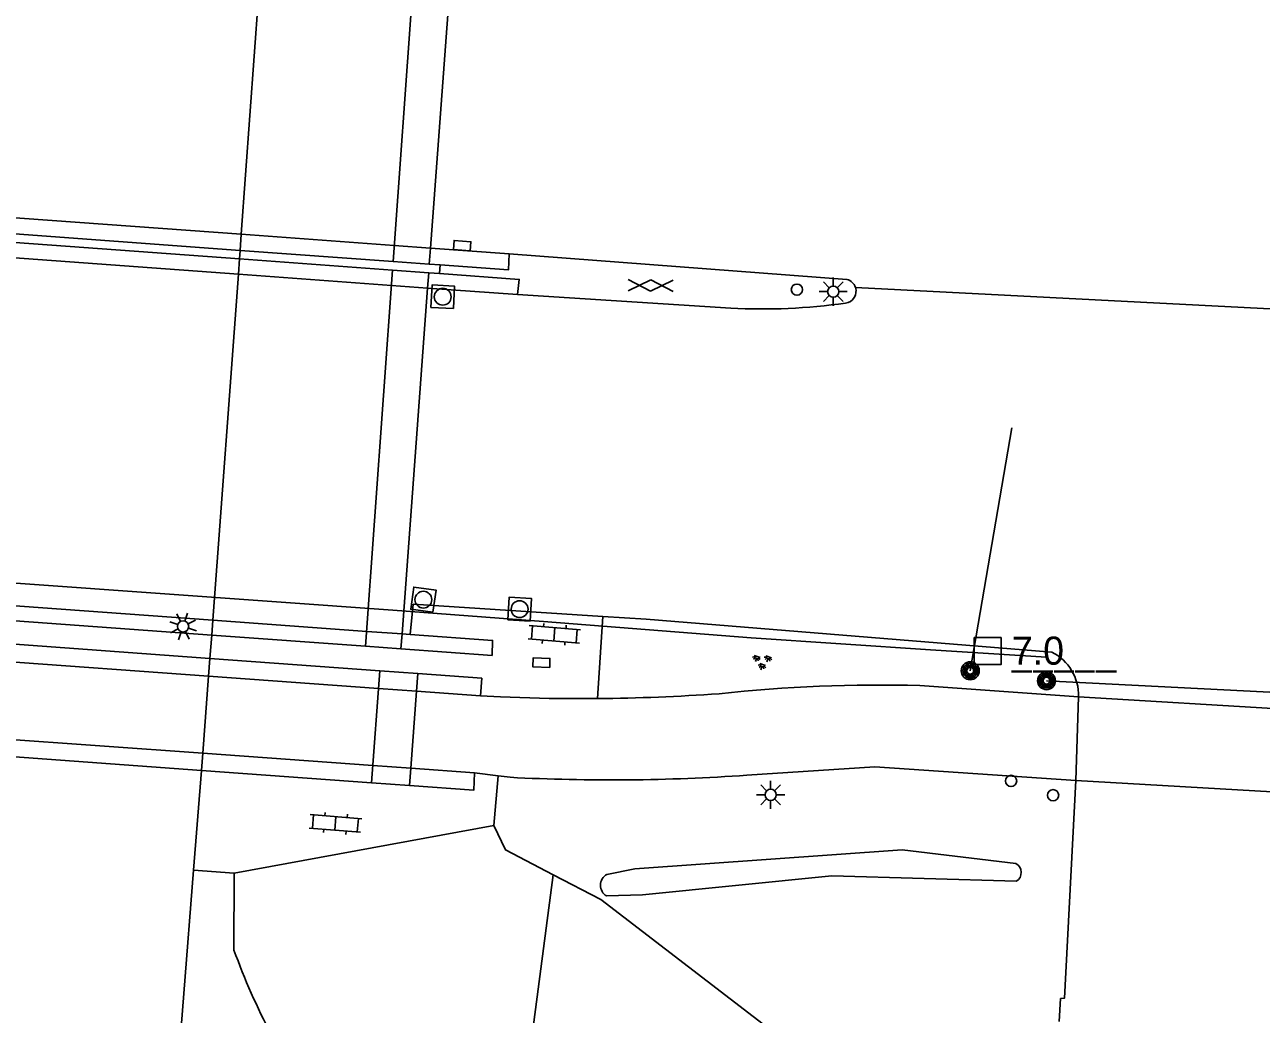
# Model space of a CAD drawing. Extents: x 133000 to 136000, y 400500 to 403500.
# Drawn here: x 133137.7 to 133192.8, y 401011.6 to 401055.6 of the extents above; entities that cross this region are included whole.
import ezdxf

# ---------------------------------------------------------------- set-up
doc = ezdxf.new("R2010")
doc.units = 0
for name, color, linetype in [('gg-knt-BGT kruinlijn', 7, 'Continuous'), ('gg-knt-bovenkant onderkant talud', 7, 'Continuous'), ('gg-knt-verharding', 7, 'Continuous'), ('gg-knt-verharding nz', 7, 'Continuous'), ('gg-kntw-greppel-droge sloot', 7, 'Continuous'), ('gg-kwrk-kunstwerk', 7, 'Continuous'), ('gg-kwrk-kunstwerk niveau 01', 7, 'Continuous'), ('gt-anno-nummer hm paal', 7, 'Continuous'), ('gt-grn-groengrens', 7, 'Continuous'), ('gt-grn-weggrens', 7, 'Continuous'), ('gt-knt-geleideconstructie', 7, 'Continuous'), ('gt-knt-lijn portaal', 7, 'Continuous'), ('gt-symb-drukknoppaal', 7, 'Continuous'), ('gt-symb-gesloten verharding', 7, 'Continuous'), ('gt-symb-groenvak', 7, 'Continuous'), ('gt-symb-hm paal', 7, 'Continuous'), ('gt-symb-klinker verharding', 7, 'Continuous'), ('gt-symb-kolk', 7, 'Continuous'), ('gt-symb-kolk center center', 7, 'Continuous'), ('gt-symb-lichtmast', 7, 'Continuous'), ('gt-symb-portaalmast', 7, 'Continuous'), ('gt-symb-rioolschacht', 7, 'Continuous'), ('gt-symb-verkeersregelinstallatiepaal', 7, 'Continuous')]:
    doc.layers.add(name, color=color, linetype=linetype)

# ---------------------------------------------------------------- blocks, each defined once
blk = doc.blocks.new('gt0-GESVH1')
at = {"layer": 'gt-symb-gesloten verharding'}
for p, q in [((-0.992, -0.261), (0.008, 0.239)), ((0.008, -0.261), (-0.992, 0.239)), ((0.008, 0.239), (1.008, -0.261)), ((1.008, 0.239), (0.008, -0.261))]:
    blk.add_line(p, q, dxfattribs=at)
blk = doc.blocks.new('gt0-GRVAK')
at = {"layer": 'gt-symb-groenvak'}
for p, q in [((-0.11, 0.189), (-0.228, 0.24)), ((-0.182, 0.153), (0.088, 0.153)), ((-0.091, 0.211), (-0.156, 0.322)), ((-0.047, 0.214), (-0.047, 0.393)), ((-0.004, 0.211), (0.061, 0.322)), ((0.015, 0.189), (0.133, 0.24)), ((0.262, -0.052), (0.197, 0.059)), ((0.305, -0.049), (0.305, 0.13)), ((0.349, -0.052), (0.414, 0.059)), ((-0.245, -0.228), (-0.363, -0.177)), ((-0.318, -0.264), (-0.047, -0.264)), ((-0.226, -0.206), (-0.291, -0.095)), ((-0.183, -0.203), (-0.183, -0.024)), ((-0.139, -0.206), (-0.074, -0.095)), ((-0.12, -0.228), (-0.002, -0.177)), ((0.243, -0.074), (0.125, -0.023)), ((0.17, -0.11), (0.441, -0.11)), ((0.368, -0.074), (0.486, -0.023))]:
    blk.add_line(p, q, dxfattribs=at)
blk = doc.blocks.new('gt0-VIPAAL')
at = {"layer": 'gt-symb-verkeersregelinstallatiepaal'}
blk.add_circle((0, 0), 0.25, dxfattribs=at)
blk = doc.blocks.new('gt0-LMAST')
at = {"layer": 'gt-symb-lichtmast'}
for p, q in [((-0.005, 0.246), (-0.005, 0.621)), ((-0.182, 0.173), (-0.447, 0.438)), ((0.172, 0.173), (0.437, 0.438)), ((-0.255, -0.004), (-0.63, -0.004)), ((-0.182, -0.181), (-0.447, -0.446)), ((-0.005, -0.254), (-0.005, -0.629)), ((0.437, -0.446), (0.172, -0.181)), ((0.245, -0.004), (0.62, -0.004))]:
    blk.add_line(p, q, dxfattribs=at)
blk.add_circle((-0.005, -0.004), 0.25, dxfattribs=at)
blk = doc.blocks.new('gt0-PORTM')
at = {"layer": 'gt-symb-portaalmast'}
for radius in [0.4, 0.33, 0.27, 0.21, 0.15]:
    blk.add_circle((0, 0), radius, dxfattribs=at)
blk = doc.blocks.new('gt0-HMpaal')
at = {"layer": 'gt-symb-hm paal'}
blk.add_lwpolyline([(-0.6, 0.6), (0.6, 0.6), (0.6, -0.6), (-0.6, -0.6)], close=True, dxfattribs=at)
blk = doc.blocks.new('gt0-DPAAL')
at = {"layer": 'gt-symb-drukknoppaal'}
blk.add_circle((0, 0), 0.25, dxfattribs=at)
blk = doc.blocks.new('gt0-KOLK')
at = {"layer": 'gt-symb-kolk'}
blk.add_lwpolyline([(0, 0), (0.375, 0), (0.375, 0.4), (-0.375, 0.4), (-0.375, 0), (0, 0)], dxfattribs=at)
blk = doc.blocks.new('gt0-KOLKCC')
at = {"layer": 'gt-symb-kolk center center'}
blk.add_lwpolyline([(-0.375, 0.2), (0.375, 0.2), (0.375, -0.2), (-0.375, -0.2)], close=True, dxfattribs=at)
blk = doc.blocks.new('gt0-KL1')
at = {"layer": 'gt-symb-klinker verharding'}
for p, q in [((-1.15, 0.3), (1.15, 0.3)), ((-1, -0.3), (-1, 0.3)), ((-0.5, 0.3), (-0.5, 0.45)), ((0, -0.3), (0, 0.3)), ((0.5, 0.3), (0.5, 0.45)), ((1, -0.3), (1, 0.3)), ((-1.15, -0.3), (1.15, -0.3)), ((-0.5, -0.45), (-0.5, -0.3)), ((0.5, -0.45), (0.5, -0.3))]:
    blk.add_line(p, q, dxfattribs=at)
blk = doc.blocks.new('gt0-RS')
at = {"layer": 'gt-symb-rioolschacht'}
blk.add_lwpolyline([(-0.5, -0.5), (0.5, -0.5), (0.5, 0.5), (-0.5, 0.5)], close=True, dxfattribs=at)
blk.add_circle((0, 0), 0.375, dxfattribs=at)

msp = doc.modelspace()

# ---------------------------------------------------------------- linework, layer by layer
at = {"layer": 'gg-knt-BGT kruinlijn'}
msp.add_lwpolyline([(133179.897, 401002.606), (133179.501, 401003.732), (133174.882, 401007.87), (133163.368, 401016.705), (133161.251, 401017.809)], dxfattribs=at)
at = {"layer": 'gg-knt-bovenkant onderkant talud'}
msp.add_line((133147.055, 401017.874), (133147.04, 401014.454), dxfattribs=at)
msp.add_lwpolyline([(133161.251, 401017.809), (133159.133, 401018.912), (133158.61, 401020.001)], dxfattribs=at)
msp.add_arc((133175.322, 401024.718), 30.087, 199.9466, 215.6251, dxfattribs=at)
at = {"layer": 'gg-knt-verharding'}
for p, q in [((133147.314, 401045.592), (133147.285, 401045.211)), ((133159.294, 401045.442), (133174.33, 401044.296)), ((133156.182, 401044.561), (133156.213, 401044.942)), ((133169.152, 401043.022), (133159.656, 401043.622)), ((133163.457, 401029.305), (133163.228, 401025.65)), ((133146.047, 401028.475), (133145.97, 401027.433)), ((133184.638, 401025.73), (133177.577, 401026.226)), ((133145.593, 401022.453), (133145.244, 401018.006)), ((133158.803, 401022.211), (133157.754, 401022.344)), ((133158.61, 401020.001), (133158.803, 401022.211)), ((133159.328, 401022.144), (133158.803, 401022.211)), ((133158.61, 401020.001), (133147.055, 401017.874)), ((133147.055, 401017.874), (133145.244, 401018.006)), ((133183.774, 401011.281), (133183.829, 401012.309))]:
    msp.add_line(p, q, dxfattribs=at)
for points in [[(133154.89, 401028.498), (133155.019, 401029.848), (133163.457, 401029.305)], [(133163.457, 401029.305), (133165.388, 401029.181), (133183.442, 401027.719)], [(133163.228, 401025.65), (133161.065, 401025.658), (133158.908, 401025.719), (133158.02, 401025.766)], [(133184.521, 401021.999), (133175.568, 401022.61), (133169.875, 401022.239)], [(133183.829, 401012.309), (133184.006, 401012.313), (133184.521, 401021.999)], [(133145.244, 401018.006), (133143.952, 401001.542), (133140.687, 400961.849), (133137.071, 400921.674), (133133.793, 400886.411), (133130.554, 400853.339), (133126.957, 400817.784)]]:
    msp.add_lwpolyline(points, dxfattribs=at)
for centre, radius, start, end in [((133174.2, 401043.777), 0.535, 18.1891, 75.8905), ((133174.198, 401043.776), 0.537, 277.3466, 18.2315), ((133170.576, 401069.26), 26.277, 266.8945, 278.0758), ((133182.472, 401025.781), 2.167, 358.64, 63.3976), ((133162.512, 401112.929), 87.282, 270.46972, 274.02176), ((133175.835, 400958.995), 67.254, 88.51538, 96.14618), ((133163.822, 401108.741), 86.714, 267.02932, 274.00281)]:
    msp.add_arc(centre, radius, start, end, dxfattribs=at)
at = {"layer": 'gg-knt-verharding nz'}
for p, q in [((133148.349, 401059.962), (133147.366, 401046.307)), ((133147.366, 401046.307), (133147.314, 401045.592)), ((133147.285, 401045.211), (133147.235, 401044.53)), ((133147.235, 401044.53), (133146.096, 401029.137)), ((133146.096, 401029.137), (133146.047, 401028.475)), ((133145.97, 401027.433), (133145.912, 401026.643)), ((133145.912, 401026.643), (133145.652, 401023.215)), ((133184.521, 401021.999), (133184.638, 401025.73)), ((133184.638, 401025.73), (133202.437, 401024.645)), ((133145.652, 401023.215), (133145.593, 401022.453)), ((133184.521, 401021.999), (133197.902, 401021.238))]:
    msp.add_line(p, q, dxfattribs=at)
at = {"layer": 'gg-kntw-greppel-droge sloot'}
for points in [[(133181.852, 401018.306), (133176.785, 401018.914), (133164.887, 401018.07), (133163.635, 401017.825)], [(133163.626, 401016.864), (133165.222, 401016.917), (133173.648, 401017.762), (133181.87, 401017.52)]]:
    msp.add_lwpolyline(points, dxfattribs=at)
for centre, radius, start, end in [((133181.636, 401017.908), 0.453, 301.0724, 61.5514), ((133163.914, 401017.342), 0.558, 119.9866, 238.9402)]:
    msp.add_arc(centre, radius, start, end, dxfattribs=at)
at = {"layer": 'gg-kwrk-kunstwerk'}
for p, q in [((133155.199, 401060.151), (133154.123, 401045.095)), ((133155.789, 401045.696), (133159.294, 401045.442)), ((133154.095, 401044.713), (133152.9, 401027.977)), ((133155.708, 401044.596), (133156.182, 401044.561)), ((133156.213, 401044.942), (133155.736, 401044.977)), ((133155.658, 401043.914), (133159.656, 401043.622)), ((133154.523, 401028.525), (133154.89, 401028.498)), ((133153.533, 401026.882), (133153.169, 401021.901)), ((133158.02, 401025.766), (133155.164, 401025.973)), ((133157.754, 401022.344), (133154.906, 401022.549))]:
    msp.add_line(p, q, dxfattribs=at)
for points in [[(133159.294, 401045.442), (133159.255, 401044.72), (133156.213, 401044.942)], [(133156.182, 401044.561), (133159.738, 401044.301), (133159.656, 401043.622)], [(133154.89, 401028.498), (133158.554, 401028.232), (133158.528, 401027.568), (133154.474, 401027.862)], [(133155.223, 401026.759), (133158.072, 401026.551), (133158.02, 401025.766)], [(133154.848, 401021.779), (133157.715, 401021.57), (133157.754, 401022.344)]]:
    msp.add_lwpolyline(points, dxfattribs=at)
at = {"layer": 'gg-kwrk-kunstwerk niveau 01'}
for p, q in [((133156.795, 401059.337), (133155.789, 401045.696)), ((133135.38, 401047.177), (133147.366, 401046.307)), ((133147.314, 401045.592), (133135.327, 401046.466)), ((133147.366, 401046.307), (133154.174, 401045.813)), ((133135.3, 401046.087), (133147.285, 401045.211)), ((133154.174, 401045.813), (133155.789, 401045.696)), ((133155.789, 401045.696), (133155.736, 401044.977)), ((133135.25, 401045.407), (133147.235, 401044.53)), ((133147.285, 401045.211), (133154.095, 401044.713)), ((133154.123, 401045.095), (133147.314, 401045.592)), ((133154.095, 401044.713), (133155.708, 401044.596)), ((133155.736, 401044.977), (133154.123, 401045.095)), ((133155.708, 401044.596), (133155.658, 401043.914)), ((133147.235, 401044.53), (133154.046, 401044.032)), ((133154.046, 401044.032), (133155.658, 401043.914)), ((133155.658, 401043.914), (133154.523, 401028.525)), ((133134.111, 401030.007), (133146.096, 401029.137)), ((133146.047, 401028.475), (133134.062, 401029.345)), ((133146.096, 401029.137), (133152.947, 401028.639)), ((133152.947, 401028.639), (133154.523, 401028.525)), ((133145.97, 401027.433), (133133.982, 401028.307)), ((133152.9, 401027.977), (133146.047, 401028.475)), ((133154.523, 401028.525), (133154.474, 401027.862)), ((133145.912, 401026.643), (133133.92, 401027.513)), ((133154.474, 401027.862), (133152.9, 401027.977)), ((133153.533, 401026.882), (133145.97, 401027.433)), ((133153.476, 401026.095), (133145.912, 401026.643)), ((133155.223, 401026.759), (133153.533, 401026.882)), ((133155.164, 401025.973), (133155.223, 401026.759)), ((133155.164, 401025.973), (133153.476, 401026.095)), ((133154.906, 401022.549), (133155.164, 401025.973)), ((133145.652, 401023.215), (133133.655, 401024.079)), ((133133.597, 401023.327), (133145.593, 401022.453)), ((133153.225, 401022.67), (133145.652, 401023.215)), ((133154.906, 401022.549), (133153.225, 401022.67)), ((133145.593, 401022.453), (133153.169, 401021.901)), ((133154.848, 401021.779), (133154.906, 401022.549)), ((133153.169, 401021.901), (133154.848, 401021.779))]:
    msp.add_line(p, q, dxfattribs=at)
at = {"layer": 'gt-grn-groengrens'}
msp.add_line((133161.251, 401017.809), (133158.808, 400999.282), dxfattribs=at)
at = {"layer": 'gt-grn-weggrens'}
msp.add_line((133195.869, 401042.844), (133174.708, 401043.944), dxfattribs=at)
at = {"layer": 'gt-knt-geleideconstructie'}
msp.add_lwpolyline([(133077.665, 401034.623), (133086.347, 401034.161), (133094.282, 401033.772), (133100.939, 401033.422), (133106.246, 401033.008), (133154.115, 401029.585), (133160.824, 401029.074), (133170.069, 401028.353), (133178.054, 401027.816), (133183.212, 401027.497)], dxfattribs=at)
at = {"layer": 'gt-knt-lijn portaal'}
for p, q in [((133179.818, 401026.886), (133181.664, 401037.695)), ((133194.025, 401025.894), (133183.212, 401026.443))]:
    msp.add_line(p, q, dxfattribs=at)

# ---------------------------------------------------------------- block references
at = {"layer": 'gt-symb-drukknoppaal', "rotation": -4.265010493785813}
msp.add_blockref('gt0-DPAAL', (133181.635, 401021.985), dxfattribs=at)
at = {"layer": 'gt-symb-gesloten verharding', "rotation": 179.08334574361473}
msp.add_blockref('gt0-GESVH1', (133165.598, 401044.02), dxfattribs=at)
at = {"layer": 'gt-symb-groenvak', "rotation": 161.27513193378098}
msp.add_blockref('gt0-GRVAK', (133170.583, 401027.319), dxfattribs=at)
at = {"layer": 'gt-symb-hm paal'}
msp.add_blockref('gt0-HMpaal', (133180.588, 401027.759), dxfattribs=at)
at = {"layer": 'gt-symb-klinker verharding'}
for p, rotation in [((133161.3, 401028.506), 175.3552783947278), ((133151.557, 401020.092), 175.35527839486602)]:
    msp.add_blockref('gt0-KL1', p, dxfattribs=dict(at, rotation=rotation))
at = {"layer": 'gt-symb-kolk', "rotation": -4.30201112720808}
msp.add_blockref('gt0-KOLK', (133157.183, 401045.605), dxfattribs=at)
at = {"layer": 'gt-symb-kolk center center', "rotation": 178.22439947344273}
msp.add_blockref('gt0-KOLKCC', (133160.727, 401027.248), dxfattribs=at)
at = {"layer": 'gt-symb-lichtmast'}
for p in [(133173.724, 401043.759), (133170.936, 401021.368)]:
    msp.add_blockref('gt0-LMAST', p, dxfattribs=at)
at = {"layer": 'gt-symb-lichtmast', "rotation": 161.27513193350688}
msp.add_blockref('gt0-LMAST', (133144.767, 401028.854), dxfattribs=at)
at = {"layer": 'gt-symb-portaalmast'}
for p in [(133179.818, 401026.886), (133183.212, 401026.443)]:
    msp.add_blockref('gt0-PORTM', p, dxfattribs=at)
at = {"layer": 'gt-symb-rioolschacht'}
for p, rotation in [((133156.332, 401043.529), -2.750834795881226), ((133155.471, 401030.049), 82.29934460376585), ((133159.756, 401029.627), -3.4404948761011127)]:
    msp.add_blockref('gt0-RS', p, dxfattribs=dict(at, rotation=rotation))
at = {"layer": 'gt-symb-verkeersregelinstallatiepaal'}
for p, rotation in [((133172.098, 401043.845), -4.26501049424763), ((133183.505, 401021.348), -4.265010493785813)]:
    msp.add_blockref('gt0-VIPAAL', p, dxfattribs=dict(at, rotation=rotation))

# ---------------------------------------------------------------- texts
at = {"layer": 'gt-anno-nummer hm paal'}
msp.add_text('7.0', height=1.25, dxfattribs=at).set_placement((133181.669, 401027.155))
at = {"layer": 'gt-symb-hm paal'}
msp.add_text('_____', height=1.25, dxfattribs=at).set_placement((133181.669, 401027.155))

doc.saveas('drawing.dxf')
